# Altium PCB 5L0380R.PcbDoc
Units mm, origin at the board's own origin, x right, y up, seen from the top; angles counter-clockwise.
Board outline 92.97 x 50.22 mm, 2 copper layers (Top Layer, Bottom Layer); 44 components, 25 nets, 105 pads, 84 vias.
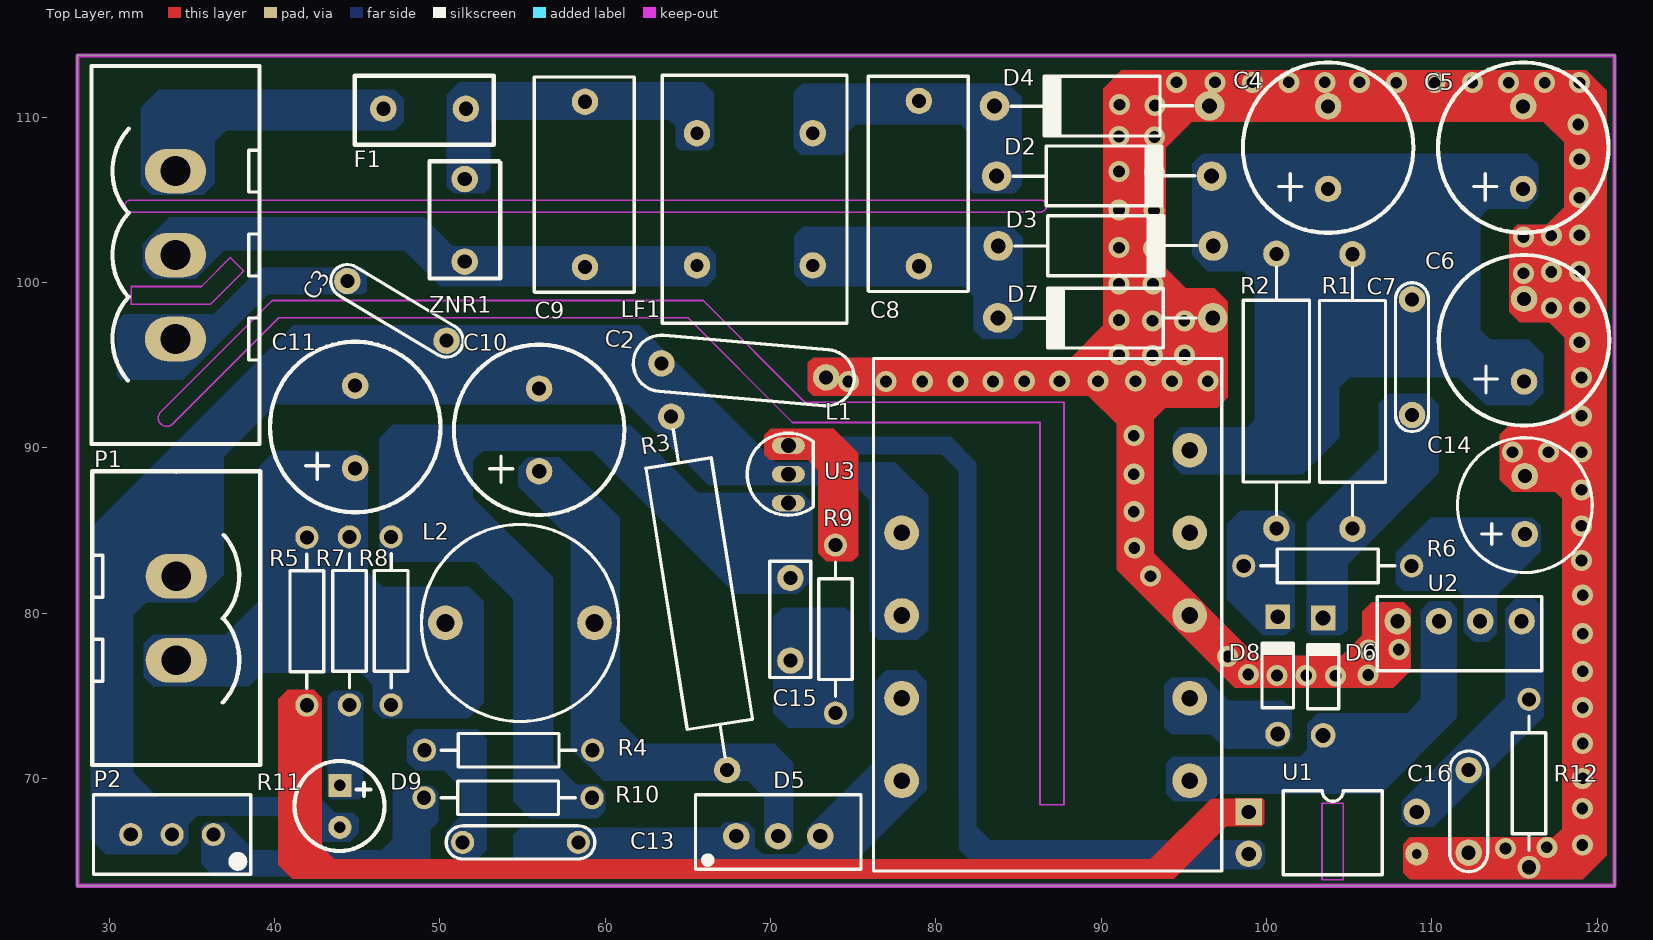
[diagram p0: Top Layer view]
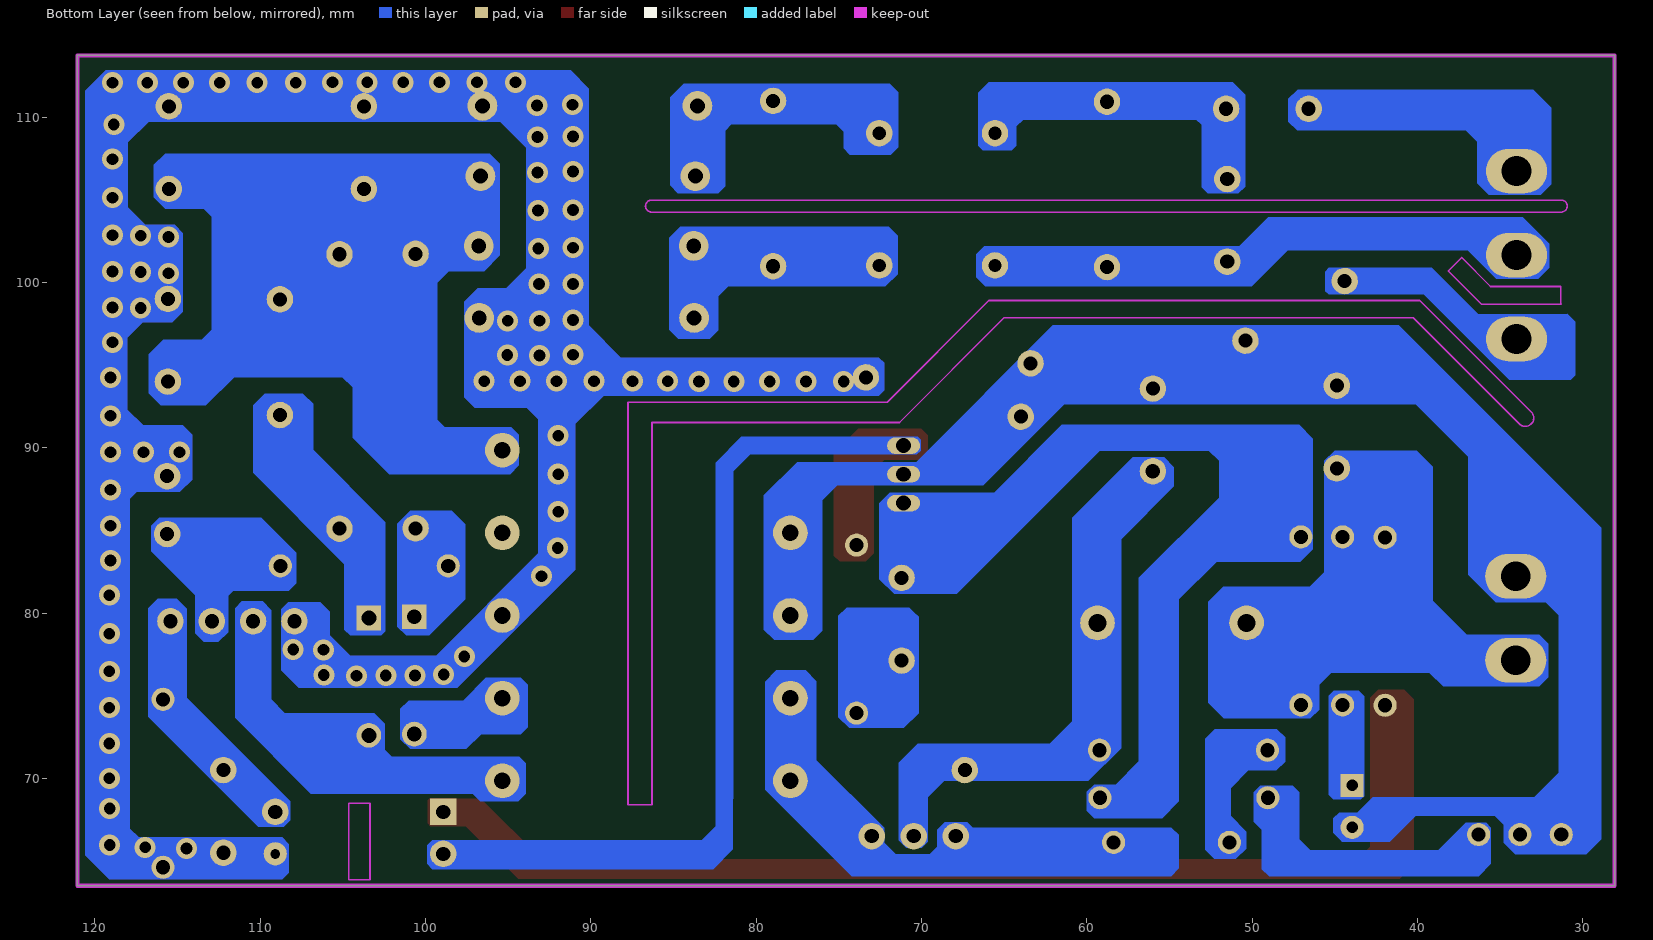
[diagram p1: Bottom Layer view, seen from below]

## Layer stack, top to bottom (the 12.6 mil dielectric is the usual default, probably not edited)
Top Solder: solder mask 0.0102, Solder Resist, Dk 3.5
Top Layer: signal copper 0.0356
Dielectric 1: dielectric 0.32, FR-4, Dk 4.8
Bottom Layer: signal copper 0.0356
Bottom Solder: solder mask 0.0102, Solder Resist, Dk 3.5

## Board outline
28.075,63.5 28.075,113.725 121.05,113.725 121.05,63.5

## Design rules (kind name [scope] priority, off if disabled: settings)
Clearance [All] p1: gap=0.254
MinimumSolderMaskSliver [All] p1 off: minsoldermaskwidth=0.254
PolygonConnect [All] p1: connectstyle=Relief reliefconductorwidth=0.254 reliefentries=4 polygonreliefangle="90 Angle" airgapwidth=0.254
RoutingVias [All] p1: holewidth=0.711 width=1.27 viastyle="Through Hole" minholewidth=0.711 minwidth=1.27 maxholewidth=0.711 maxwidth=1.27
SilkToSilkClearance [All] p1 off: silktosilkclearance=0.254
SilkToSolderMaskClearance [IsPad] p1 off: minsilkscreentomaskgap=0.254 clearancetoexposedcopper=TRUE
SolderMaskExpansion [All] p1: expansion=0.102
Width [All] p1: maxlimit=0.254 minlimit=0.254 preferedwidth=0.254
26 further rules are at their usual default settings.

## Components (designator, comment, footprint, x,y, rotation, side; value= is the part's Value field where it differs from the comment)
C2 "2.2NF" "Y电容 2.2NF" 63.4,95.1 r355 top
C3 "103 2KV" 2KV电容#1 50.4,96.475 r149 top
C4 "10UF 400V" "10UF 400v"#1 103.725,105.65 r90 top
C5 "10UF 400V" "10UF 400v"#1 115.525,105.65 r90 top
C6 "10UF 400V" "10UF 400v"#1 115.575,94 r90 top
C7 "103 2KV" 2KV电容#1 108.8,91.975 r90 top
C8 "0.1UF 220V" X电容 78.975,100.975 r90 top
C9 "0.1UF 220V" X电容 58.775,100.925 r90 top
C10 "1000UF 25V" "10UF 400v"#2 56,88.575 r90 top
C11 "1000UF 25V" "10UF 400v"#1 44.875,88.75 r90 top
C13 "102 1KV" 2KV电容#2 51.375,66.125 r0 top
C14 "10UF 50V" "25V 100UF" 115.625,84.775 r90 top
C15 "104J 100V" "100J 100V" 71.2,77.125 r90 top
C16 "33NF 100V" "33NF 100V电容" 112.225,70.5 r270 top
D2 "Diode 1N4007" 整流二极管 83.675,106.425 r0 top
D3 "Diode 1N4007" 整流二极管 83.775,102.2 r0 top
D4 "Diode 1N4007" 整流二极管 96.55,110.675 r180 top
D5 "MBRF20100CT" MBRF20100CT 67.925,66.5 r0 top
D6 "FR107 1A1000V 快恢复整流二极管" DO-35 103.425,76.15 r90 top
D7 "Diode 1N4007" 整流二极管 96.75,97.85 r180 top
D8 "FR104 1A 400V" DO-35 100.675,76.225 r90 top
D9 "LED0" 插件LED 43.95,69.575 r270 top
F1 "3.15AL/250Vac" 熔断丝 46.575,110.5 r0 top
L1 "变压器5L0380R" 变压器 95.35,89.85 r0 top locked
L2 "Inductor" 滤波电感 59.35,79.4 r180 top
LF1 "T18*8*7" 共模电感 72.55,109.025 r0 top
P1 "Header 3" HDR3X1_D1 34,101.65 r90 top
P2 "OUT" HEX2 34.05,82.225 r270 top
R1 "47K 1W" 1W电阻 105.2,85.1 r90 top
R2 "510K 1W" 1W电阻 100.6,85.125 r90 top
R3 "470R 2W" 2W电阻 67.375,70.5 r99 top
R4 "15R" AXIAL-0.4 54.15,71.7 r0 top
R5 "220R" AXIAL-0.4 41.95,79.5 r270 top
R6 "10R" AXIAL-0.4 103.7,82.85 r0 top
R7 "2.2K" AXIAL-0.4 44.525,79.525 r270 top
R8 "10K" AXIAL-0.4 47.05,79.525 r270 top
R9 "510R" AXIAL-0.4 73.925,79.025 r270 top
R10 "2.2K" AXIAL-0.4 54.125,68.825 r180 top
R11 "RPot" 100R滑动变阻器 36.3,66.6 r180 top
R12 "8.2K" AXIAL-0.4 115.875,69.7 r270 top
U1 "PC817" PC817 98.925,67.975 r0 top
U2 "5L0380R" 5L0380R 107.925,79.5 r0 top
U3 "AZ431" TL431 71.075,86.65 r0 top
ZNR1 "ZNR" 压敏电阻 51.5,101.25 r90 top

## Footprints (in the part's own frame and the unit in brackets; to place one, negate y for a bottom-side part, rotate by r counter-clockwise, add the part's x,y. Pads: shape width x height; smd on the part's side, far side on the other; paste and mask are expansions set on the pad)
1W电阻 [mm]
  round 1.6 hole 0.85: 1(0,0) 2(16.6,0)
  silkscreen extent 0.8,-2 15.8,2
2KV电容#1 [mm]
  round 1.6 hole 0.85: 1(0,0) 2(7,0)
  silkscreen extent -1,-1 8,1
2KV电容#2 [mm]
  round 1.4 hole 0.85: 1(0,0) 2(7,0)
  silkscreen extent -1,-1 8,1
2W电阻 [mm]
  round 1.6 hole 0.85: 1(0,0) 2(21.641,0)
  silkscreen extent 0.8,-2 20.85,2
5L0380R [mm]
  round 1.6 hole 0.85: 1(0,0) 2(2.5,0) 3(5,0) 4(7.5,0)
  silkscreen extent -1.22,-3 8.72,1.5
"10UF 400v"#1 [mm]
  round 1.6 hole 0.85: 1(0,0) 2(5,0)
  silkscreen extent -2.65,-5.16 7.65,5.16
"10UF 400v"#2 [mm]
  round 1.6 hole 0.885: 1(0,0)
  round 1.6 hole 0.85: 2(5,0)
  silkscreen extent -2.65,-5.16 7.65,5.16
"25V 100UF" [mm]
  round 1.6 hole 0.85: 1(0,0) 2(3.5,0)
  silkscreen extent -2.33,-4.08 5.83,4.08
"33NF 100V电容" [mm]
  round 1.6 hole 0.85: 1(0,0) 2(5,0)
  silkscreen extent -1.15,-1.15 6.15,1.15
"100J 100V" [mm]
  round 1.6 hole 0.85: 1(0,0) 2(5,0)
  silkscreen extent -1.02,-1.22 6,1.25
100R滑动变阻器 [mm]
  round 1.4 hole 0.85: 1(0,0) 2(2.5,0) 3(5,0)
  silkscreen extent -2.25,-2.4 7.25,2.4
AXIAL-0.4 [mm] "Axial Device, Thru-Hole; 2 Leads; 0.4 in Pin Spacing"
  round 1.4 hole 0.85: 1(-5.08,0) 2(5.08,0)
  silkscreen extent -4.06,-1.02 4.06,1.02
DO-35 [mm] "Diode, Axial; Body 3.8 x 1.9 mm (LxDia. max), Lead Dia. 0.53 mm (max)"
  round 1.5 hole 0.9: 1(-3.55,0)
  rect 1.5x1.5 hole 0.9: 2(3.55,0)
  silkscreen extent -1.95,-0.95 2.05,0.95
HDR3X1_D1 [mm] "5.08mm端子"
  oval 2.7x3.7 hole 1.8: 1(-5.08,0) 2(0,0) 3(5.08,0)
  silkscreen extent -11.43,-5.08 11.43,5.08
HEX2 [mm]
  oval 2.7x3.7 hole 1.8: 1(0,0) 2(5.08,0)
  silkscreen extent -6.35,-5.08 11.42,5.08
MBRF20100CT [mm]
  round 1.6 hole 0.85: 1(0,0) 2(2.54,0) 3(5.08,0)
  silkscreen extent -2.46,-2.01 7.54,2.51
PC817 [mm]
  rect 1.6x1.6 hole 0.85: 1(0,0)
  round 1.6 hole 0.85: 2(0,-2.54) 4(10.16,0)
  round 1.4 hole 0.6: 3(10.16,-2.54)
  silkscreen extent 2.08,-3.81 8.08,1.27
TL431 [mm]
  oval 2x1 hole 0.9: 1(0,0) 2(0,1.745) 3(0,3.475)
  silkscreen extent -2.48,-0.74 1.5,4.23, body extent -2.5,-0.75 1.5,4.24, height 6.86
X电容 [mm]
  round 1.6 hole 0.85: 1(0,0) 2(10,0)
  silkscreen extent -1.53,-2.98 11.5,3.08
"Y电容 2.2NF" [mm]
  round 1.6 hole 0.85: 1(0,0) 2(10,0.025)
  silkscreen extent -1.7,-1.7 11.7,1.7
共模电感 [mm]
  round 1.6 hole 0.8: 1(0,0) 2(0,-8) 3(-7,0) 4(-7,-8)
  silkscreen extent -9.1,-11.5 2.07,3.5
压敏电阻 [mm]
  round 1.6 hole 0.85: 1(0,0) 2(5,0)
  silkscreen extent -1.02,-2.15 6.07,2.13
变压器 [mm]
  round 2.1 hole 1: 1(0,0) 2(0,-5) 3(0,-10) 4(0,-15) 5(0,-20) 6(-17.424,-20) 7(-17.424,-15) 8(-17.424,-10) 9(-17.424,-5)
  silkscreen extent -19.13,-25.45 1.95,5.55
插件LED [mm]
  rect 1.4x1.4 hole 0.7: 1(0,0)
  round 1.4 hole 0.7: 2(2.54,0)
  silkscreen extent -1.47,-2.75 3.97,2.7
整流二极管 [mm]
  round 1.8 hole 0.9: 1(0,0) 2(13,0)
  silkscreen extent 1,-1.8 12,1.85
滤波电感 [mm]
  round 2.1 hole 1.1: 1(0,0) 2(9.017,0)
  silkscreen extent -1.45,-5.96 10.47,5.96
熔断丝 [mm]
  round 1.6 hole 0.85: 1(0,0) 2(5,0)
  silkscreen extent -1.73,-2.17 6.67,2

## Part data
C2 C3 C7 C8 C9 C13 C15 C16: library part Cap, "Capacitor"
C4 C5 C6 C10 C11 C14: library part CAP1, "Electronic Capacitor"
D2 D3 D4 D7: "1 Amp General Purpose Rectifier"
D5: library part MRF20100CT
D6: library part "Diode 1N914", "High Conductance Fast Diode"
D8: library part "Diode 1N4006", "1 Amp General Purpose Rectifier"
D9: "Typical INFRARED GaAs LED"
F1: library part FUSE
LF1: library part TRANSFORMER
P1: "Header, 3-Pin"
P2: library part "Header 2", "Header, 2-Pin"
R1 R2 R3 R4 R5 R6 R7 R8 R9 R10 R12: library part Res, "resistance"
R11: "Potentiometer"
U1: library part Optoisolator1, "4-Pin Phototransistor Optocoupler"
U3: library part 431

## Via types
v1: diameter 1.27, hole 0.711, Top Layer to Bottom Layer, tented both sides, 84 vias

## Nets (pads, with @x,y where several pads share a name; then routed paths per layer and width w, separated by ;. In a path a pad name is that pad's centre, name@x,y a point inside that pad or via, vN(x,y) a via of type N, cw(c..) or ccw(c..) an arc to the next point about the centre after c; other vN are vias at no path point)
EARTH: C3.2 P1.1
GND: C2.2 C4.2 C5.2 C6.2 C14.2 C16.2 D4.1 D7.1 L1.3 R12.2 U1.3 U2.1
  other v1: 114.45,65.75 116.95,65.825 119.1,65.975 119.1,68.175 119.125,70 119.125,72.1 119.125,74.275 104.175,76.2 100.625,76.225 102.4,76.225 106.15,76.25 98.9,76.275 119.125,76.475 97.65,77.375 106.175,77.775 108,77.8 119.125,78.75 119.125,81.075 92.975,82.225 119.05,83.175 92,83.925 119.05,85.275 91.975,86.125 119.05,87.45 91.975,88.4 114.875,89.725 117.05,89.725 119.05,89.725 91.975,90.725 119.05,91.925 74.7,94 76.975,94 79.175,94 81.35,94 83.45,94 85.35,94.025 87.475,94.025 89.8,94.025 92.075,94.025 94.275,94.025 96.45,94.025 119.05,94.25 93.1,95.575 95.05,95.6 91.075,95.625 118.925,96.375 93.1,97.675 95.025,97.675 91.075,97.725 117.225,98.45 118.925,98.475 91.075,99.9 93.125,99.9 115.55,100.55 117.225,100.625 118.925,100.65 93.175,102.05 91.075,102.1 115.55,102.75 117.225,102.825 118.925,102.85 93.2,104.35 91.075,104.375 118.925,105.125 93.225,106.65 91.075,106.7 118.925,107.45 93.225,108.8 91.075,108.825 118.85,109.55 93.25,110.7 91.1,110.75 107.85,112.075 110.175,112.075 112.45,112.075 114.65,112.075 116.825,112.075 118.925,112.075 94.55,112.1 96.875,112.1 99.15,112.1 101.35,112.1 103.525,112.1 105.625,112.1
NetC2_1: C2.1 C3.1 C10.2 C11.2 D9.2 L1.8 L1.9 P2.1 R3.2 R11.2 R11.3 U3.2
NetC4_1: C4.1 C5.1 C6.1 C7.2 D2.2 D3.2 L1.1 R1.2 R2.2
NetC7_1: C7.1 D6.2 R1.1
NetC8_1: C8.1 D3.1 D7.2 LF1.2
NetC8_2: C8.2 D2.1 D4.2 LF1.1
NetC9_1: C9.1 LF1.4 P1.2 ZNR1.1
NetC9_2: C9.2 F1.2 LF1.3 ZNR1.2
NetC10_1: C10.1 D5.2 L2.1 R3.1 R4.2
NetC11_1: C11.1 L2.2 P2.2 R5.1 R7.1 R8.2
NetC13_1: C13.1 R4.1
NetC13_2: C13.2 D5.1 D5.3 L1.6 L1.7
NetC14_1: C14.1 R6.2 U2.3
NetC15_1: C15.1 R9.2
NetC15_2: C15.2 R8.1 R10.1 U3.1
NetC16_1: C16.1 R12.1 U1.4 U2.4
NetD6_1: D6.1 L1.5 U2.2
NetD8_1: D8.1 L1.4
NetD8_2: D8.2 R2.1 R6.1
NetD9_1: D9.1 R7.2
NetF1_1: F1.1 P1.3
NetR5_2: R5.2 U1.1
NetR9_1: R9.1 U1.2 U3.3
NetR10_2: R10.2 R11.1
pads on no net: L1.2

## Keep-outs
Keep-Out Layer:
  lines w0.1: 33.112,92.162 ccw(c33.475,91.8) 33.838,91.437 ; 33.125,92.175 39.85,98.9 65.925,98.9 72.075,92.75 87.75,92.75 87.75,68.4 86.3,68.4 86.3,91.525 85.075,91.525 ; 33.875,91.475 40.25,97.85 65,97.85 71.325,91.525 85.1,91.525 ; 31.3,98.675 36.125,98.675 38.138,100.687 37.325,101.5 35.575,99.75 31.325,99.75 31.325,98.7 31.3,98.675 ; 31.3,104.25 cw(c31.3,104.613) 31.3,104.975 86.325,104.975 cw(c86.325,104.613) 86.325,104.25 31.3,104.25 ; 103.35,63.875 104.65,63.875 104.65,68.475 104.625,68.5 103.35,68.5 103.35,63.875
  lines w0.254: 28.075,63.5 28.075,113.725 121.05,113.725 121.05,63.5 28.075,63.5

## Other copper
Top Layer:
  region net NetR9_1: 75.3,83.475 75.3,89.675 73.825,91.15 70.025,91.15 69.625,90.75 69.625,89.6 69.95,89.275 72.25,89.275 72.875,88.65 72.875,83.625 73.375,83.125 74.95,83.125
  region net NetR5_2: 98.15,68.8 99.75,68.8 99.875,68.675 99.875,67.275 99.7,67.1 97.575,67.1 94.4,63.925 41.075,63.925 40.225,64.775 40.225,74.775 40.8,75.35 42.375,75.35 42.85,74.875 42.85,65.85 43.6,65.1 92.975,65.1 96.65,68.775 98.15,68.775
  region net GND: 72.575,95.45 72.25,95.125 72.25,93.475 72.575,93.15
  region net GND: 118.05,104.575 116.95,103.475 115.175,103.475 114.675,102.975 114.675,98.225 115.306,97.594 117.819,97.594 118.175,97.95 118.05,98.075
  region net GND: 93.862,92.425 97.025,92.425 97.65,93.05 97.65,98.825 96.825,99.65 95.1,99.65 93.82,100.93
  region net GND: 72.575,93.15 72.575,95.45 88.175,95.45 90.125,97.4 90.125,111.725 91.225,112.825 119.325,112.825 120.575,111.575 120.575,65.35 119.125,63.9 108.675,63.9 108.275,64.3 108.275,66.025 108.675,66.425 117.35,66.425 117.875,66.95 117.875,86.9 117.45,87.325 114.85,87.325 114.1,88.075 114.1,90.775 114.675,91.35 117.075,91.35 118.025,92.3 118.025,96.65 115.588,99.088 118,101.5 118,108.475 116.75,109.725 95.475,109.725 93.9,108.15 93.9,92.45 93.175,91.725 93.175,83.6 99.35,77.425 104.55,77.425 105.775,78.65 105.775,80.075 106.35,80.65 108.3,80.65 108.725,80.225 108.725,76.55 107.65,75.475 98.075,75.475 90.925,82.625 90.925,91.45 89.225,93.15
Bottom Layer:
  region net NetC15_1: 70.175,79.775 70.175,73.95 71.075,73.05 74.375,73.05 75.025,73.7 75.025,79.825 74.525,80.325 70.725,80.325 70.487,80.088
  region net NetC10_1: 55.325,89.425 57.225,89.425 60.875,85.775 60.875,73.45 62.225,72.1 70.225,72.1 71.375,70.95 71.375,66.25 70.925,65.8 69.975,65.8 69.625,66.15 69.625,68.85 68.625,69.85 59.9,69.85 57.925,71.825 57.925,84.475 54.725,87.675 54.725,88.825
  region net NetC15_2: 71.65,81.15 67.875,81.15 59.2,89.825 52.625,89.825 52,89.2 52,86.975 56.85,82.125 56.85,71.025 58.25,69.625 59.55,69.625 60,69.175 60,68.05 59.55,67.6 55.425,67.6 54.425,68.6 54.425,80.825 52.15,83.1 47.075,83.1 46.325,83.85 46.325,90.55 47.15,91.375 61.5,91.375 65.6,87.275 71.925,87.275 72.55,86.65 72.55,82.05
  region net NetC11_1: 45.625,89.2 45,89.825 40.05,89.825 39.075,88.85 39.075,80.75 37,78.675 32.625,78.675 32.1,78.15 32.1,76.1 32.625,75.575 38.45,75.575 39.275,76.4 45.225,76.4 45.95,75.675 45.95,74.15 46.475,73.625 51.7,73.625 52.65,74.575 52.65,80.675 51.75,81.575 46.525,81.575 45.625,82.475
  region net NetR10_2: 35.55,67 35.55,64.825 36.3,64.075 48.975,64.075 49.4,64.5 49.4,66.875 49.9,67.375 49.9,69.15 49.5,69.55 47.55,69.55 47.15,69.15 47.15,66.325 46.475,65.65 38.725,65.65 37.075,67.3 35.85,67.3
  region net NetC2_1: 44.575,66.175 41.675,66.175 40.1,67.75 35.325,67.75 34.775,67.2 34.775,66.1 34.075,65.4 29.775,65.4 28.875,66.3 28.875,85.15 41.125,97.4 62.05,97.4 70.325,89.125 77.525,89.125 79.525,87.125 79.525,79 78.9,78.375 76.55,78.375 76,78.925 76,86.825 75.1,87.725 66.275,87.725 61.375,92.625 40.1,92.625 36.925,89.45 36.925,82.325 35.25,80.65 32.25,80.65 31.45,79.85 31.45,70.325 32.925,68.85 42.7,68.85 43.625,67.925 44.725,67.925 45.075,67.575 45.075,66.7 44.575,66.2
  region net NetD9_1: 45.35,75 45.05,75.3 43.55,75.3 43.225,74.975 43.225,68.925 43.425,68.725 45.075,68.725 45.35,69
  region net NetC13_1: 52.25,72.975 52.825,72.4 52.825,65.675 52.275,65.125 50.975,65.125 50.35,65.75 50.35,66.775 51.3,67.725 51.3,69.4 50.225,70.475 48.525,70.475 48,71 48,72.475 48.5,72.975
  region net NetC13_2: 76.35,71.1 76.35,75.875 77,76.525 78.775,76.525 79.45,75.85 79.45,69.3 74.225,64.075 54.9,64.075 54.425,64.55 54.425,66.575 54.875,67.025 66.9,67.025 67.225,67.35 68.6,67.35 69.05,66.9 69.05,65.85 69.5,65.4 71.55,65.4 72.25,66.1 72.25,67
  region net NetC16_1: 114.45,80.25 115.05,80.85 116.2,80.85 116.775,80.275 116.775,73.725 110.125,67.075 108.575,67.075 108.175,67.475 108.175,68.6 114.45,74.875
  region net NetD8_1: 94.225,76.075 96.35,76.075 97.725,74.7 101.025,74.7 101.525,74.2 101.525,72.375 100.925,71.775 97.525,71.775 96.625,72.675 94.225,72.675 93.825,73.075 93.825,75.675
  region net NetD6_1: 93.925,69.075 94.375,68.625 96.7,68.625 97.15,69.075 106.925,69.075 111.5,73.65 111.5,80.3 111.1,80.7 109.85,80.7 109.325,80.175 109.325,74.775 108.5,73.95 103.1,73.95 102.45,73.3 102.45,71.725 102.025,71.3 94.325,71.3 93.925,70.9
  region net NetC14_1: 109.925,85.75 116.1,85.75 116.575,85.275 116.575,83.725 113.925,81.075 113.925,78.775 113.4,78.25 112.525,78.25 111.925,78.85 111.925,81.05 111.625,81.35 108.275,81.35 107.825,81.8 107.825,83.65
  region net NetD8_2: 101.175,78.65 99.775,78.65 97.6,80.825 97.6,85.375 98.4,86.175 100.925,86.175 101.7,85.4 101.7,79.175
  region net NetC7_1: 102.425,78.9 102.675,78.65 104.55,78.65 104.9,79 104.9,82.95 110.425,88.475 110.425,92.575 109.725,93.275 107.425,93.275 106.8,92.65 106.8,89.875 102.425,85.5
  region net NetC4_1: 115.75,107.775 116.425,107.1 116.425,105.15 115.725,104.45 113.4,104.45 112.925,103.975 112.925,97.125 113.525,96.525 115.85,96.525 116.725,95.65 116.725,93.3 116,92.575 113.275,92.575 111.575,94.275 105.025,94.275 104.4,93.65 104.4,90.6 102.2,88.4 94.875,88.4 94.35,88.925 94.35,90.775 94.8,91.225 98.825,91.225 99.3,91.7 99.3,99.975 98.6,100.675 96.45,100.675 95.5,101.625 95.5,107.175 96.1,107.775
  region net NetR9_1: 70.275,89.6 70.05,89.825 70.05,90.475 70.225,90.65 80.9,90.65 82.45,89.1 82.45,67.1 83.3,66.25 99.6,66.25 99.9,65.95 99.9,64.825 99.575,64.5 82.6,64.5 81.4,65.7 81.4,68.75 81.375,68.775 81.375,88.575 80.35,89.6
  region net NetF1_1: 31.9,110.55 33,111.65 47.25,111.65 47.8,111.1 47.8,109.725 47.275,109.2 37.075,109.2 36.375,108.5 36.375,106 35.675,105.3 32.525,105.3 31.9,105.925
  region net NetC9_2: 50.425,111.35 51.175,112.1 65.925,112.1 66.55,111.475 66.55,108.25 66.3,108 64.525,108 64.25,108.275 64.25,109.45 63.85,109.85 53.375,109.85 53.05,109.525 53.05,105.75 52.675,105.375 50.825,105.375 50.425,105.775
  region net NetC8_2: 71.4,111.5 71.925,112.025 84.375,112.025 85.2,111.2 85.2,105.875 84.725,105.4 82.3,105.4 81.875,105.825 81.875,109.175 81.5,109.55 75.15,109.55 74.7,109.1 74.7,108.1 74.325,107.725 71.85,107.725 71.4,108.175
  region net NetC8_1: 71.425,100.5 71.425,102.825 71.975,103.375 84.575,103.375 85.25,102.7 85.25,97.125 84.7,96.575 82.8,96.575 82.275,97.1 82.3,97.125 82.3,99.15 81.7,99.75 72.175,99.75
  region net EARTH: 30.925,98.1 36.325,98.075 39.125,100.875 45.35,100.875 45.575,100.65 45.575,99.475 45.375,99.275 39.625,99.275 34.45,94.1 30.725,94.1 30.45,94.375 30.45,97.625
  region net NetC9_1: 32.025,102.325 33.625,103.925 49.025,103.925 50.775,102.175 66.2,102.175 66.675,101.7 66.675,100.3 66.15,99.775 50.025,99.775 47.85,101.95 36.95,101.95 35.225,100.225 32.675,100.225 32.025,100.875
  region net GND: 72.575,93.15 72.575,95.45 88.175,95.45 90.125,97.4 90.125,111.725 91.225,112.825 119.325,112.825 120.575,111.575 120.575,65.35 119.125,63.9 108.675,63.9 108.275,64.3 108.275,66.025 108.675,66.425 117.35,66.425 117.875,66.95 117.875,86.9 117.45,87.325 114.85,87.325 114.1,88.075 114.1,90.775 114.675,91.35 117.075,91.35 118.025,92.3 118.025,96.65 115.588,99.088 118,101.5 118,108.475 116.75,109.725 95.475,109.725 93.9,108.15 93.9,92.45 93.175,91.725 93.175,83.6 99.35,77.425 104.55,77.425 105.775,78.65 105.775,80.075 106.35,80.65 108.3,80.65 108.725,80.225 108.725,76.55 107.65,75.475 98.075,75.475 90.925,82.625 90.925,91.45 89.225,93.15
  region net GND: 93.862,92.425 97.025,92.425 97.65,93.05 97.65,98.825 96.825,99.65 95.1,99.65 93.82,100.93
  region net GND: 118.05,104.575 116.95,103.475 115.175,103.475 114.675,102.975 114.675,98.225 115.306,97.594 117.819,97.594 118.175,97.95 118.05,98.075
  region net GND: 72.575,95.45 72.25,95.125 72.25,93.475 72.575,93.15

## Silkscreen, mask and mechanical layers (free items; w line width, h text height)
Bottom Solder:
  drawing of 180 lines, arcs and shapes, not listed
  text "93.075 (mm)" at 66.844,116.503 h1.52 r0.06
  text "50.2 (mm)" at 126.464,82.254 h1.52 r90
